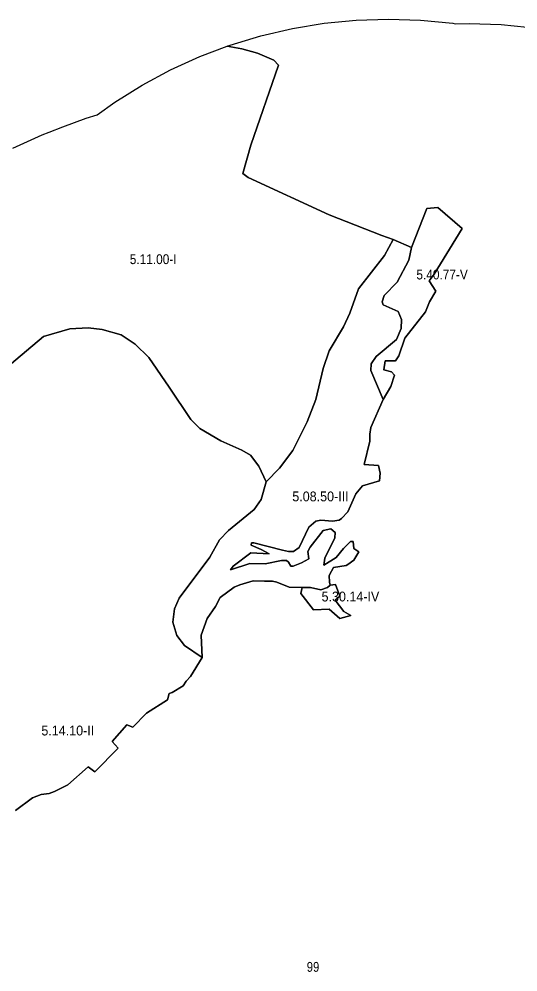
# Model space of a CAD drawing. Extents: x -591496 to -585489, y -1120610 to -1115685.
# Drawn here: x -590065 to -589052, y -1117620 to -1115685 of the extents above; entities that cross this region are included whole.
import ezdxf

# ---------------------------------------------------------------- set-up
doc = ezdxf.new("R2010")
doc.units = 0
doc.header["$LTSCALE"] = 8
doc.layers.add('40', color=7, linetype='Continuous', lineweight=25)
doc.layers.add('41', color=7, linetype='Continuous')

msp = doc.modelspace()

# ---------------------------------------------------------------- linework, layer by layer
at = {"layer": '40'}
for points in [[(-589517.5, -1116766), (-589507, -1116766), (-589496, -1116757.5), (-589476, -1116716.5), (-589462, -1116704), (-589451.5, -1116702.5), (-589428, -1116704.5), (-589414.5, -1116702.5), (-589409.5, -1116699), (-589397, -1116685.5), (-589381, -1116649), (-589367.5, -1116632.5), (-589332.5, -1116622.5), (-589331.5, -1116607), (-589335, -1116591), (-589364, -1116589), (-589352.5, -1116542), (-589352.5, -1116527.5), (-589350, -1116514), (-589325, -1116457), (-589309.5, -1116431), (-589302.5, -1116407.5), (-589308, -1116401), (-589324, -1116397), (-589321, -1116378.5), (-589300, -1116379), (-589293.5, -1116368.5), (-589281, -1116333), (-589239, -1116279), (-589231, -1116259), (-589218.5, -1116237.5), (-589231.5, -1116216), (-589222, -1116202.5), (-589165, -1116110), (-589214, -1116067.5), (-589236.5, -1116069.5), (-589267.5, -1116148.5), (-589305, -1116132.5), (-589328, -1116124), (-589435, -1116082.5), (-589599.5, -1116006.5), (-589610, -1115998.5), (-589594, -1115940.5), (-589538, -1115778), (-589547.5, -1115768), (-589580.5, -1115754), (-589612.5, -1115745), (-589641.87, -1115739.892), (-589635.939, -1115737.66), (-589573.319, -1115718.664), (-589509.59, -1115703.805), (-589445.026, -1115693.145), (-589379.903, -1115686.731), (-589314.5, -1115684.59), (-589249.097, -1115686.731), (-589183.974, -1115693.145)], [(-589183.974, -1115693.145), (-589178.735, -1115694.01), (-589150.83, -1115693.49), (-589085.427, -1115695.631), (-589033.025, -1115700.792)], [(-590077.239, -1115946.907), (-590017.633, -1115919.9), (-590003.571, -1115914.2), (-589975.781, -1115903.18), (-589928.6, -1115885.83), (-589906.259, -1115879.053), (-589870.07, -1115853.12), (-589814.5, -1115818.565), (-589756.789, -1115787.717), (-589697.183, -1115760.711), (-589641.87, -1115739.892), (-589612.5, -1115745), (-589580.5, -1115754), (-589547.5, -1115768), (-589538, -1115778), (-589594, -1115940.5), (-589610, -1115998.5), (-589599.5, -1116006.5), (-589435, -1116082.5), (-589328, -1116124), (-589305, -1116132.5), (-589322.5, -1116164.5), (-589375, -1116232.5), (-589393, -1116282), (-589405.5, -1116309.5), (-589435, -1116358.5), (-589447, -1116394.5), (-589462, -1116457.5), (-589479.5, -1116502.5), (-589508.5, -1116560.5), (-589536, -1116597), (-589562.5, -1116624.5), (-589578, -1116592.5), (-589594.5, -1116570.5), (-589612, -1116560), (-589655, -1116541.5), (-589697.5, -1116516), (-589715.5, -1116498), (-589759.5, -1116432.5), (-589801, -1116372), (-589828.5, -1116345), (-589857.5, -1116326), (-589896, -1116315), (-589924, -1116311.5), (-589961.5, -1116313.5), (-590015, -1116329.5), (-590106.5, -1116406)], [(-589536, -1116597), (-589508.5, -1116560.5), (-589479.5, -1116502.5), (-589462, -1116457.5), (-589447, -1116394.5), (-589435, -1116358.5), (-589405.5, -1116309.5), (-589393, -1116282), (-589375, -1116232.5), (-589322.5, -1116164.5), (-589305, -1116132.5), (-589267.5, -1116148.5)], [(-589267.5, -1116148.5), (-589273, -1116174), (-589297, -1116219), (-589323.5, -1116246), (-589327, -1116259), (-589325, -1116265), (-589294.5, -1116278.5), (-589288, -1116295), (-589288.5, -1116313), (-589298, -1116335.5), (-589339.5, -1116370), (-589349.5, -1116384.5), (-589350.5, -1116398), (-589325, -1116457), (-589350, -1116514), (-589352.5, -1116527.5), (-589352.5, -1116542), (-589364, -1116589), (-589335, -1116591), (-589331.5, -1116607), (-589332.5, -1116622.5), (-589367.5, -1116632.5), (-589381, -1116649), (-589397, -1116685.5), (-589409.5, -1116699), (-589414.5, -1116702.5), (-589428, -1116704.5), (-589451.5, -1116702.5), (-589462, -1116704), (-589476, -1116716.5), (-589496, -1116757.5), (-589507, -1116766), (-589517.5, -1116766), (-589529.5, -1116763.5), (-589588, -1116748), (-589592.5, -1116748), (-589593.5, -1116753), (-589573, -1116762), (-589557, -1116770.5), (-589594, -1116768.5), (-589629.5, -1116796), (-589635, -1116803), (-589596, -1116790), (-589564.5, -1116791), (-589532, -1116784), (-589521.5, -1116784), (-589517.5, -1116787.5), (-589512.5, -1116796), (-589508, -1116795.5), (-589491, -1116789), (-589476.5, -1116780.5), (-589478, -1116766), (-589473.5, -1116757), (-589447, -1116723.5), (-589431.5, -1116720), (-589422.5, -1116727.5), (-589423.5, -1116738), (-589444, -1116779.5), (-589446, -1116794), (-589421, -1116778), (-589405.5, -1116760), (-589391.5, -1116745.5), (-589386, -1116745.5), (-589385, -1116760), (-589374.5, -1116766.5), (-589385, -1116783.5), (-589397, -1116792), (-589400.5, -1116794.5), (-589426, -1116798.5), (-589430, -1116806), (-589435, -1116814.5), (-589434.5, -1116828), (-589433, -1116834.5), (-589438, -1116839), (-589452, -1116844), (-589473, -1116839), (-589489.5, -1116839), (-589516, -1116838.5), (-589541, -1116828.5), (-589550, -1116826.5), (-589566, -1116826), (-589589.5, -1116825.5), (-589616.5, -1116833.5), (-589628, -1116838.5), (-589656.5, -1116859.5), (-589666, -1116877.5), (-589682.5, -1116902), (-589695, -1116936), (-589692.5, -1116981), (-589728.5, -1116956.5), (-589744, -1116936.5), (-589752, -1116909.5), (-589749, -1116882.5), (-589739.5, -1116861), (-589677.5, -1116777.5), (-589657.5, -1116742.5), (-589639, -1116723), (-589587, -1116680.5), (-589573, -1116660), (-589562.5, -1116624.5), (-589536, -1116597)], [(-590106.5, -1116406), (-590015, -1116329.5), (-589961.5, -1116313.5), (-589924, -1116311.5), (-589896, -1116315), (-589857.5, -1116326), (-589828.5, -1116345), (-589801, -1116372), (-589759.5, -1116432.5), (-589715.5, -1116498), (-589697.5, -1116516), (-589655, -1116541.5), (-589612, -1116560), (-589594.5, -1116570.5), (-589578, -1116592.5), (-589562.5, -1116624.5)], [(-589562.5, -1116624.5), (-589573, -1116660), (-589587, -1116680.5), (-589639, -1116723), (-589657.5, -1116742.5), (-589677.5, -1116777.5), (-589739.5, -1116861), (-589749, -1116882.5), (-589752, -1116909.5), (-589744, -1116936.5), (-589728.5, -1116956.5), (-589692.5, -1116981), (-589716.5, -1117019.5), (-589725, -1117029.5), (-589731.5, -1117038.5), (-589754, -1117052), (-589760, -1117054), (-589763, -1117067), (-589805.5, -1117094), (-589833.5, -1117123), (-589846, -1117118), (-589875.5, -1117152), (-589863.5, -1117165), (-589911, -1117213.5), (-589924, -1117203), (-589965.5, -1117239.5), (-589992.5, -1117253.5), (-590003.5, -1117257.5), (-590020, -1117259.5), (-590037.5, -1117266.5), (-590072, -1117292)], [(-590072, -1117292), (-590037.5, -1117266.5), (-590020, -1117259.5), (-590003.5, -1117257.5), (-589992.5, -1117253.5), (-589965.5, -1117239.5), (-589924, -1117203), (-589911, -1117213.5), (-589863.5, -1117165), (-589875.5, -1117152), (-589846, -1117118), (-589833.5, -1117123), (-589805.5, -1117094), (-589763, -1117067), (-589760, -1117054), (-589754, -1117052), (-589731.5, -1117038.5), (-589725, -1117029.5), (-589716.5, -1117019.5), (-589692.5, -1116981), (-589695, -1116936), (-589682.5, -1116902), (-589666, -1116877.5), (-589656.5, -1116859.5), (-589628, -1116838.5), (-589616.5, -1116833.5), (-589589.5, -1116825.5), (-589566, -1116826), (-589550, -1116826.5), (-589541, -1116828.5), (-589516, -1116838.5), (-589489.5, -1116839), (-589492.5, -1116851.5), (-589467, -1116884.5), (-589435, -1116883), (-589413, -1116902), (-589391, -1116896), (-589405, -1116888), (-589422.5, -1116864.5), (-589413, -1116856.5), (-589422.043, -1116832.733), (-589433, -1116834.5), (-589434.5, -1116828), (-589435, -1116814.5), (-589430, -1116806), (-589426, -1116798.5), (-589400.5, -1116794.5), (-589397, -1116792), (-589385, -1116783.5), (-589374.5, -1116766.5), (-589385, -1116760), (-589386, -1116745.5), (-589391.5, -1116745.5), (-589405.5, -1116760), (-589421, -1116778), (-589446, -1116794), (-589444, -1116779.5), (-589423.5, -1116738), (-589422.5, -1116727.5), (-589431.5, -1116720), (-589447, -1116723.5), (-589473.5, -1116757), (-589478, -1116766), (-589476.5, -1116780.5), (-589491, -1116789), (-589508, -1116795.5), (-589512.5, -1116796), (-589517.5, -1116787.5), (-589521.5, -1116784), (-589532, -1116784), (-589564.5, -1116791), (-589596, -1116790), (-589635, -1116803), (-589629.5, -1116796), (-589594, -1116768.5), (-589557, -1116770.5), (-589573, -1116762), (-589593.5, -1116753), (-589592.5, -1116748), (-589588, -1116748), (-589529.5, -1116763.5), (-589517.5, -1116766)]]:
    msp.add_lwpolyline(points, dxfattribs=at)
for points in [[(-589325, -1116457), (-589350.5, -1116398), (-589349.5, -1116384.5), (-589339.5, -1116370), (-589298, -1116335.5), (-589288.5, -1116313), (-589288, -1116295), (-589294.5, -1116278.5), (-589325, -1116265), (-589327, -1116259), (-589323.5, -1116246), (-589297, -1116219), (-589273, -1116174), (-589267.5, -1116148.5), (-589236.5, -1116069.5), (-589214, -1116067.5), (-589165, -1116110), (-589222, -1116202.5), (-589231.5, -1116216), (-589218.5, -1116237.5), (-589231, -1116259), (-589239, -1116279), (-589281, -1116333), (-589293.5, -1116368.5), (-589300, -1116379), (-589321, -1116378.5), (-589324, -1116397), (-589308, -1116401), (-589302.5, -1116407.5), (-589309.5, -1116431)], [(-589489.5, -1116839), (-589473, -1116839), (-589452, -1116844), (-589438, -1116839), (-589433, -1116834.5), (-589422.043, -1116832.733), (-589413, -1116856.5), (-589422.5, -1116864.5), (-589405, -1116888), (-589391, -1116896), (-589413, -1116902), (-589435, -1116883), (-589467, -1116884.5), (-589492.5, -1116851.5)]]:
    msp.add_lwpolyline(points, close=True, dxfattribs=at)

# ---------------------------------------------------------------- texts
at = {"layer": '41'}
for s, width, p in [('5.11.00-I', 0.9, (-589839.75, -1116182.25)), ('5.40.77-V', 0.9, (-589257.75, -1116213.375)), ('5.08.50-III', 0.95, (-589509.75, -1116664.063)), ('5.30.14-IV', 0.95, (-589450.313, -1116867.375)), ('5.14.10-II', 0.95, (-590019.25, -1117139.5)), ('99', 0.85, (-589480.281, -1117619.5))]:
    msp.add_text(s, height=20, dxfattribs=dict(at, width=width)).set_placement(p)

doc.saveas('drawing.dxf')
